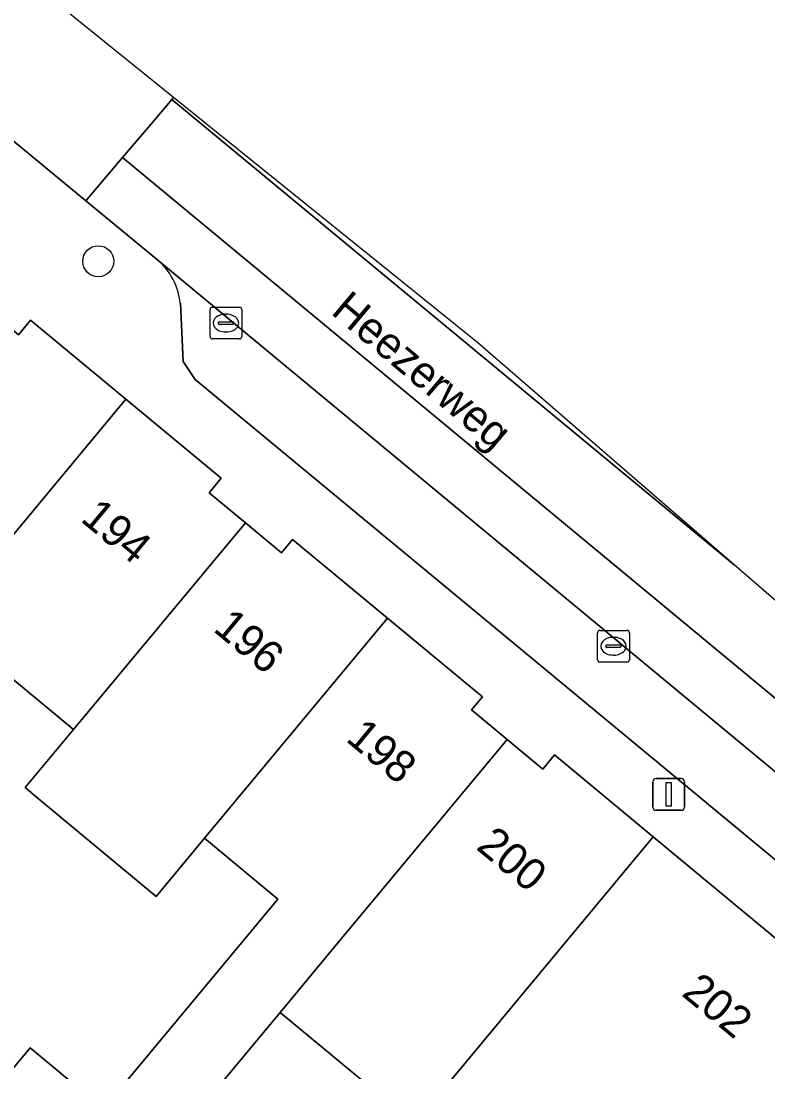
# Model space of a CAD drawing. Extents: x 161881 to 162523, y 381678 to 382381.
# Drawn here: x 162388.24 to 162411.76, y 381897.16 to 381930.28 of the extents above; entities that cross this region are included whole.
import ezdxf

# ---------------------------------------------------------------- set-up
doc = ezdxf.new("R2010")
doc.units = 0
for name, color, linetype in [('IMGEO_Boom', 7, 'Continuous'), ('IMGEO_Erf', 7, 'Continuous'), ('IMGEO_Kolk', 7, 'Continuous'), ('IMGEO_Lichtmast', 7, 'Continuous'), ('IMGEO_Openbare_ruimte_label', 7, 'Continuous'), ('IMGEO_Pand', 7, 'Continuous'), ('IMGEO_Pand_nummerreeks', 7, 'Continuous'), ('IMGEO_Parkeervlak_open', 7, 'Continuous'), ('IMGEO_Rijbaan_lokaal_gesloten', 7, 'Continuous'), ('IMGEO_Rijbaan_lokaal_open', 7, 'Continuous'), ('IMGEO_Voetpad_open', 7, 'Continuous')]:
    doc.layers.add(name, color=color, linetype=linetype)

msp = doc.modelspace()

# ---------------------------------------------------------------- linework, layer by layer
at = {"layer": 'IMGEO_Boom'}
msp.add_circle((162390.676, 381922.708), 0.489, dxfattribs=at)
at = {"layer": 'IMGEO_Erf'}
for points in [[(162383.306, 381891.633), (162388.53, 381897.921), (162390.835, 381896.006), (162396.322, 381902.611), (162394.016, 381904.526), (162392.495, 381902.696), (162388.778, 381905.783), (162388.37, 381906.122), (162389.891, 381907.952), (162385.752, 381911.39), (162381.619, 381914.822), (162380.911, 381915.41), (162377.065, 381918.605), (162372.654, 381913.683), (162372.054, 381913.013), (162369.869, 381910.575), (162373.57, 381907.213), (162375.958, 381905.043), (162371.892, 381900.569), (162371.822, 381900.491), (162373.921, 381898.584), (162369.929, 381894.191), (162365.442, 381898.267), (162361.741, 381901.629)], [(162400.608, 381895.546), (162396.401, 381899.041), (162391.15, 381892.722)]]:
    msp.add_lwpolyline(points, dxfattribs=at)
at = {"layer": 'IMGEO_Kolk'}
for p, q in [((162394.193, 381920.333), (162394.193, 381921.185)), ((162394.268, 381921.259), (162395.12, 381921.259)), ((162395.194, 381921.185), (162395.194, 381920.333)), ((162394.681, 381921.039), (162394.706, 381921.039)), ((162394.452, 381920.753), (162394.452, 381920.765)), ((162394.89, 381920.716), (162394.492, 381920.716)), ((162394.495, 381920.802), (162394.893, 381920.802)), ((162394.936, 381920.765), (162394.936, 381920.753)), ((162395.12, 381920.259), (162394.268, 381920.259)), ((162394.704, 381920.479), (162394.679, 381920.479)), ((162406.392, 381910.152), (162406.392, 381911.004)), ((162406.467, 381911.078), (162407.319, 381911.078)), ((162407.393, 381911.004), (162407.393, 381910.152)), ((162406.651, 381910.572), (162406.651, 381910.584)), ((162406.694, 381910.621), (162407.092, 381910.621)), ((162406.88, 381910.858), (162406.905, 381910.858)), ((162407.135, 381910.584), (162407.135, 381910.572)), ((162407.089, 381910.535), (162406.691, 381910.535)), ((162406.903, 381910.298), (162406.878, 381910.298)), ((162407.319, 381910.078), (162406.467, 381910.078))]:
    msp.add_line(p, q, dxfattribs=at)
for points in [[(162394.193, 381920.333), (162394.193, 381921.185)], [(162394.268, 381921.259), (162395.12, 381921.259)], [(162395.194, 381921.185), (162395.194, 381920.333)], [(162395.12, 381920.259), (162394.268, 381920.259)], [(162406.392, 381910.152), (162406.392, 381911.004)], [(162406.467, 381911.078), (162407.319, 381911.078)], [(162407.393, 381911.004), (162407.393, 381910.152)], [(162407.319, 381910.078), (162406.467, 381910.078)]]:
    msp.add_lwpolyline(points, dxfattribs=at)
for centre, radius, start, end in [((162394.27, 381921.183), 0.0765, 91.552, 178.448), ((162394.27, 381921.183), 0.0765, 91.552, 178.448), ((162395.118, 381921.183), 0.0765, 1.552, 88.448), ((162395.118, 381921.183), 0.0765, 1.552, 88.448), ((162394.492, 381920.762), 0.0403, 85.8775, 175.7526), ((162394.489, 381920.752), 0.0366, 178.938, 274.7102), ((162394.893, 381920.759), 0.043, 264.8664, 352.4533), ((162394.897, 381920.764), 0.0386, 1.7309, 96.639), ((162394.27, 381920.335), 0.0765, 181.552, 268.448), ((162394.27, 381920.335), 0.0765, 181.552, 268.448), ((162395.118, 381920.335), 0.0765, 271.552, 358.448), ((162395.118, 381920.335), 0.0765, 271.552, 358.448), ((162406.469, 381911.002), 0.0765, 91.552, 178.448), ((162406.469, 381911.002), 0.0765, 91.552, 178.448), ((162407.317, 381911.002), 0.0765, 1.552, 88.448), ((162407.317, 381911.002), 0.0765, 1.552, 88.448), ((162406.691, 381910.581), 0.0403, 85.8775, 175.7526), ((162406.688, 381910.571), 0.0366, 178.938, 274.7102), ((162407.092, 381910.578), 0.043, 264.8664, 352.4533), ((162407.096, 381910.583), 0.0386, 1.7309, 96.639), ((162406.469, 381910.154), 0.0765, 181.552, 268.448), ((162406.469, 381910.154), 0.0765, 181.552, 268.448), ((162407.317, 381910.154), 0.0765, 271.552, 358.448), ((162407.317, 381910.154), 0.0765, 271.552, 358.448)]:
    msp.add_arc(centre, radius, start, end, dxfattribs=at)
for centre, major_axis, ratio, start_param, end_param in [((162394.68, 381920.759), (-0.387, 0.002), 0.722429, 4.712389, 7.853982), ((162394.705, 381920.759), (-0.39, 0.002), 0.717154, 1.570796, 4.712389), ((162406.879, 381910.578), (-0.387, 0.002), 0.722429, 4.712389, 7.853982), ((162406.904, 381910.578), (-0.39, 0.002), 0.717154, 1.570796, 4.712389)]:
    msp.add_ellipse(centre, major_axis=major_axis, ratio=ratio, start_param=start_param, end_param=end_param, dxfattribs=at)
at = {"layer": 'IMGEO_Lichtmast'}
for p, q in [((162408.134, 381905.509), (162408.134, 381906.309)), ((162408.134, 381906.309), (162408.134, 381905.509)), ((162408.234, 381906.409), (162409.024, 381906.409)), ((162409.024, 381906.409), (162408.234, 381906.409)), ((162409.124, 381906.309), (162409.124, 381905.509)), ((162409.124, 381905.509), (162409.124, 381906.309)), ((162409.024, 381905.409), (162408.234, 381905.409)), ((162408.234, 381905.409), (162409.024, 381905.409))]:
    msp.add_line(p, q, dxfattribs=at)
msp.add_lwpolyline([(162408.554, 381906.284), (162408.704, 381906.284), (162408.704, 381905.534), (162408.554, 381905.534), (162408.554, 381906.284)], dxfattribs=at)
for centre, start, end in [((162408.234, 381906.309), 90, 180), ((162408.234, 381906.309), 90, 180), ((162409.024, 381906.309), 0, 90), ((162409.024, 381906.309), 360, 90), ((162408.234, 381905.509), 180, 270), ((162408.234, 381905.509), 180, 270), ((162409.024, 381905.509), 270, 0), ((162409.024, 381905.509), 270, 0)]:
    msp.add_arc(centre, 0.1, start, end, dxfattribs=at)
at = {"layer": 'IMGEO_Pand'}
for points in [[(162385.752, 381911.39), (162391.545, 381918.362), (162388.545, 381920.853), (162388.161, 381920.391), (162387.028, 381921.332), (162381.619, 381914.822)], [(162385.752, 381911.39), (162389.891, 381907.952), (162395.307, 381914.468), (162394.169, 381915.414), (162394.547, 381915.869), (162391.545, 381918.362)], [(162399.779, 381911.463), (162396.791, 381913.944), (162396.443, 381913.525), (162395.307, 381914.468), (162389.891, 381907.952), (162388.37, 381906.122), (162388.778, 381905.783), (162392.495, 381902.696), (162394.016, 381904.526)], [(162403.544, 381907.638), (162402.423, 381908.569), (162402.766, 381908.982), (162399.779, 381911.463), (162394.016, 381904.526), (162396.322, 381902.611), (162390.835, 381896.006), (162388.53, 381897.921), (162383.306, 381891.633), (162383.334, 381890.448), (162386.932, 381887.647), (162391.07, 381892.625), (162391.15, 381892.722), (162396.401, 381899.041), (162398.124, 381901.115)], [(162408.147, 381904.571), (162405.036, 381907.154), (162404.664, 381906.707), (162403.544, 381907.638), (162398.124, 381901.115), (162396.401, 381899.041), (162400.608, 381895.546), (162401.594, 381896.684)], [(162408.147, 381904.571), (162401.594, 381896.684), (162400.608, 381895.546), (162399.473, 381894.233), (162401.564, 381892.497), (162392.445, 381881.515), (162394.198, 381880.059), (162412.296, 381894.75), (162416.178, 381897.901)]]:
    msp.add_lwpolyline(points, close=True, dxfattribs=at)
at = {"layer": 'IMGEO_Parkeervlak_open'}
for points in [[(162415.872, 381903.4), (162392.553, 381922.745)], [(162393.258, 381921.387), (162393.35, 381919.549), (162393.725, 381918.977), (162413.782, 381902.355)]]:
    msp.add_lwpolyline(points, dxfattribs=at)
msp.add_arc((162391.13, 381921.145), 2.141, 6.5024, 48.3694, dxfattribs=at)
at = {"layer": 'IMGEO_Rijbaan_lokaal_gesloten'}
msp.add_lwpolyline([(162393.04, 381927.87), (162392.987, 381927.807), (162410.692, 381913.142), (162402.622, 381920.132), (162393.04, 381927.87)], dxfattribs=at)
msp.add_lwpolyline([(162438.65, 381886.825), (162391.437, 381925.971), (162390.287, 381924.609), (162392.553, 381922.745), (162415.872, 381903.4), (162415.953, 381903.333), (162424.033, 381896.682), (162424.125, 381896.606), (162436.606, 381886.219), (162437.45, 381885.369)], close=True, dxfattribs=at)
at = {"layer": 'IMGEO_Rijbaan_lokaal_open'}
for points in [[(162393.04, 381927.87), (162378.151, 381939.893), (162377.551, 381939.142), (162376.704, 381938.084), (162375.563, 381936.718), (162375.768, 381936.531)], [(162387.072, 381927.252), (162390.287, 381924.609), (162391.437, 381925.971), (162392.314, 381927.01), (162392.987, 381927.807), (162393.04, 381927.87)], [(162410.692, 381913.142), (162392.987, 381927.807), (162392.314, 381927.01), (162391.437, 381925.971), (162438.65, 381886.825), (162437.45, 381885.369)], [(162477.929, 381853.826), (162482.435, 381848.753), (162483.942, 381850.5), (162484.656, 381851.328), (162471.681, 381861.933), (162438.538, 381889.024), (162410.692, 381913.142)]]:
    msp.add_lwpolyline(points, dxfattribs=at)
at = {"layer": 'IMGEO_Voetpad_open'}
for points in [[(162380.831, 381927.406), (162383.131, 381925.342), (162386.275, 381922.731), (162385.894, 381922.274), (162387.028, 381921.332), (162388.161, 381920.391), (162388.545, 381920.853), (162391.545, 381918.362), (162394.547, 381915.869), (162394.169, 381915.414), (162395.307, 381914.468), (162396.443, 381913.525), (162396.791, 381913.944), (162399.779, 381911.463), (162402.766, 381908.982), (162402.423, 381908.569), (162403.544, 381907.638), (162404.664, 381906.707), (162405.036, 381907.154), (162408.147, 381904.571), (162416.178, 381897.901), (162417.532, 381897.014)], [(162392.553, 381922.745), (162390.287, 381924.609), (162387.072, 381927.252)], [(162393.725, 381918.977), (162393.35, 381919.549), (162393.258, 381921.387)], [(162413.782, 381902.355), (162393.725, 381918.977)]]:
    msp.add_lwpolyline(points, dxfattribs=at)
msp.add_arc((162391.13, 381921.145), 2.141, 6.5024, 48.3694, dxfattribs=at)

# ---------------------------------------------------------------- texts
at = {"layer": 'IMGEO_Openbare_ruimte_label'}
msp.add_text('Heezerweg', height=1, rotation=319.9522, dxfattribs=at).set_placement((162397.964, 381921.069))
at = {"layer": 'IMGEO_Pand_nummerreeks'}
for s, rotation, p in [('194', 320.3174, (162390.082, 381914.541)), ('196', 320.3169, (162394.256, 381911.078)), ('198', 320.3169, (162398.432, 381907.612)), ('200', 320.3174, (162402.535, 381904.208)), ('202', 320.2917, (162409.004, 381899.595))]:
    msp.add_text(s, height=1, rotation=rotation, dxfattribs=at).set_placement(p)

doc.saveas('drawing.dxf')
